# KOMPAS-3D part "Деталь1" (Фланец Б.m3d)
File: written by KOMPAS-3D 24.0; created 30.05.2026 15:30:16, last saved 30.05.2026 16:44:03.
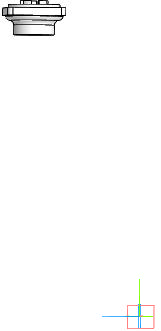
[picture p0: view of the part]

Document properties: Автор: R2D2; Полное имя файла: E:\Работа\Зайцев\GVWR2434M-2W-F-ОСТ Задвижка клиновая с выдвижным штоком DN.ru Ду50-300 Ру25\исходные материалы\DN200\Фланец Б.m3d

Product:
- Body: Твердое тело1  | qty 1
    Масса: 4.288251
- Part/product: Деталь1
    Масса: 4.288251
    additional columns: Типовые

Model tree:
1. Твердое тело1  (labels: Твердое тело1)
2. Эскиз:1  (labels: Грань.Твердое тело1; Вершина.Твердое тело1)
3. Элемент вращения:1
     Угол 1 = 360
4. Эскиз:2  (labels: Грань.Твердое тело1; Ребро.Твердое тело1)
5. Эскиз:3  (labels: Грань.Твердое тело1; Ребро.Твердое тело1)
6. Элемент выдавливания:1
     Расстояние 1 = 10
7. Элемент выдавливания:2  (labels: Грань.Твердое тело1)
     Расстояние 2 = 7
8. Эскиз:4  (labels: Грань.Твердое тело1; Ребро.Твердое тело1)
9. Элемент выдавливания:3  (labels: Грань.Твердое тело1)
     Расстояние 1 = 16
10. Эскиз:5  (labels: Грань.Твердое тело1; Ребро.Твердое тело1)
11. Элемент выдавливания:4
     Расстояние 1 = 7
12. Скругление:1  (with: Ребро.Элемент вращения:1)
     Радиус = 10
13. Скругление:2  (with: Грань.Элемент вращения:1)
     Радиус = 10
